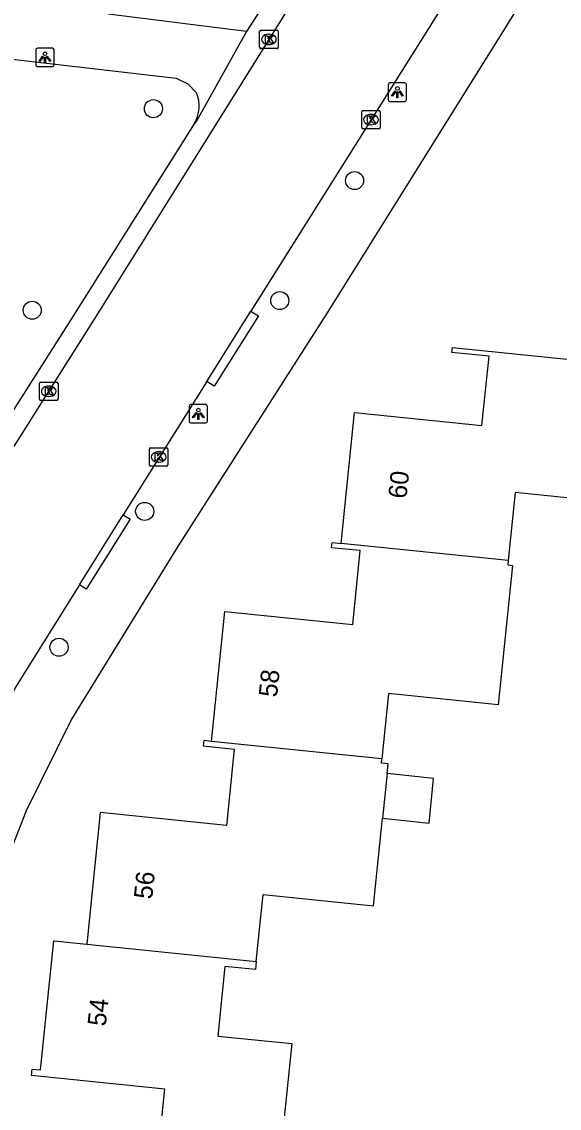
# Model space of a CAD drawing. Extents: x 162398 to 163643, y 386453 to 387397.
# Drawn here: x 162917.5 to 162946.6, y 386956.9 to 387015.8 of the extents above; entities that cross this region are included whole.
import ezdxf

# ---------------------------------------------------------------- set-up
doc = ezdxf.new("R2010")
doc.units = 0
for name, color, linetype in [('IMGEO_Boom', 7, 'Continuous'), ('IMGEO_Kolk', 7, 'Continuous'), ('IMGEO_Lichtpunt', 7, 'Continuous'), ('IMGEO_Pand', 7, 'Continuous'), ('IMGEO_Pand_nummerreeks', 7, 'Continuous'), ('IMGEO_Rijbaan_lokaal_open', 7, 'Continuous'), ('IMGEO_Voetpad_open', 7, 'Continuous')]:
    doc.layers.add(name, color=color, linetype=linetype)

msp = doc.modelspace()

# ---------------------------------------------------------------- linework, layer by layer
at = {"layer": 'IMGEO_Boom'}
for centre in [(162924.653, 387011.052), (162935.55, 387007.16), (162931.497, 387000.658), (162918.093, 387000.138), (162924.183, 386989.242), (162919.544, 386981.885)]:
    msp.add_circle(centre, 0.489, dxfattribs=at)
at = {"layer": 'IMGEO_Kolk'}
for p, q in [((162930.408, 387014.377), (162930.408, 387015.229)), ((162930.483, 387015.303), (162931.335, 387015.303)), ((162931.409, 387015.229), (162931.409, 387014.377)), ((162930.896, 387015.083), (162930.921, 387015.083)), ((162931.335, 387014.303), (162930.483, 387014.303)), ((162930.919, 387014.523), (162930.894, 387014.523)), ((162935.937, 387010.033), (162935.937, 387010.885)), ((162936.012, 387010.959), (162936.864, 387010.959)), ((162936.425, 387010.739), (162936.45, 387010.739)), ((162936.938, 387010.885), (162936.938, 387010.033)), ((162936.864, 387009.959), (162936.012, 387009.959)), ((162936.448, 387010.179), (162936.423, 387010.179)), ((162918.489, 386995.323), (162918.489, 386996.175)), ((162918.564, 386996.249), (162919.416, 386996.249)), ((162918.977, 386996.029), (162919.002, 386996.029)), ((162919.49, 386996.175), (162919.49, 386995.323)), ((162919.416, 386995.249), (162918.564, 386995.249)), ((162919, 386995.469), (162918.975, 386995.469)), ((162924.438, 386991.763), (162924.438, 386992.615)), ((162924.513, 386992.689), (162925.365, 386992.689)), ((162924.926, 386992.469), (162924.951, 386992.469)), ((162925.439, 386992.615), (162925.439, 386991.763)), ((162925.365, 386991.689), (162924.513, 386991.689)), ((162924.949, 386991.909), (162924.924, 386991.909))]:
    msp.add_line(p, q, dxfattribs=at)
for points in [[(162930.408, 387014.377), (162930.408, 387015.229)], [(162930.483, 387015.303), (162931.335, 387015.303)], [(162931.409, 387015.229), (162931.409, 387014.377)], [(162930.729, 387015.003), (162930.852, 387015.003), (162930.852, 387014.852), (162930.982, 387015.003), (162931.146, 387015.003), (162931, 387014.852), (162931.153, 387014.603), (162931.001, 387014.603), (162930.916, 387014.767), (162930.852, 387014.7), (162930.852, 387014.603), (162930.729, 387014.603), (162930.729, 387015.003)], [(162931.335, 387014.303), (162930.483, 387014.303)], [(162935.937, 387010.033), (162935.937, 387010.885)], [(162936.012, 387010.959), (162936.864, 387010.959)], [(162936.258, 387010.659), (162936.381, 387010.659), (162936.381, 387010.508), (162936.511, 387010.659), (162936.675, 387010.659), (162936.529, 387010.508), (162936.682, 387010.259), (162936.53, 387010.259), (162936.445, 387010.423), (162936.381, 387010.356), (162936.381, 387010.259), (162936.258, 387010.259), (162936.258, 387010.659)], [(162936.938, 387010.885), (162936.938, 387010.033)], [(162936.864, 387009.959), (162936.012, 387009.959)], [(162918.489, 386995.323), (162918.489, 386996.175)], [(162918.564, 386996.249), (162919.416, 386996.249)], [(162918.81, 386995.949), (162918.933, 386995.949), (162918.933, 386995.798), (162919.063, 386995.949), (162919.227, 386995.949), (162919.081, 386995.798), (162919.234, 386995.549), (162919.082, 386995.549), (162918.997, 386995.713), (162918.933, 386995.646), (162918.933, 386995.549), (162918.81, 386995.549), (162918.81, 386995.949)], [(162919.49, 386996.175), (162919.49, 386995.323)], [(162919.416, 386995.249), (162918.564, 386995.249)], [(162924.438, 386991.763), (162924.438, 386992.615)], [(162924.513, 386992.689), (162925.365, 386992.689)], [(162924.759, 386992.389), (162924.882, 386992.389), (162924.882, 386992.238), (162925.012, 386992.389), (162925.176, 386992.389), (162925.03, 386992.238), (162925.183, 386991.989), (162925.031, 386991.989), (162924.946, 386992.153), (162924.882, 386992.086), (162924.882, 386991.989), (162924.759, 386991.989), (162924.759, 386992.389)], [(162925.439, 386992.615), (162925.439, 386991.763)], [(162925.365, 386991.689), (162924.513, 386991.689)]]:
    msp.add_lwpolyline(points, dxfattribs=at)
for centre, start, end in [((162930.485, 387015.227), 91.55205, 178.44795), ((162930.485, 387015.227), 91.55205, 178.44795), ((162931.333, 387015.227), 1.55205, 88.44795), ((162931.333, 387015.227), 1.55205, 88.44795), ((162930.485, 387014.379), 181.55205, 268.44795), ((162930.485, 387014.379), 181.55205, 268.44795), ((162931.333, 387014.379), 271.55205, 358.44795), ((162931.333, 387014.379), 271.55205, 358.44795), ((162936.014, 387010.883), 91.55205, 178.44795), ((162936.014, 387010.883), 91.55205, 178.44795), ((162936.862, 387010.883), 1.55205, 88.44795), ((162936.862, 387010.883), 1.55205, 88.44795), ((162936.014, 387010.035), 181.55205, 268.44795), ((162936.014, 387010.035), 181.55205, 268.44795), ((162936.862, 387010.035), 271.55205, 358.44795), ((162936.862, 387010.035), 271.55205, 358.44795), ((162918.566, 386996.173), 91.55205, 178.44795), ((162918.566, 386996.173), 91.55205, 178.44795), ((162919.414, 386996.173), 1.55205, 88.44795), ((162919.414, 386996.173), 1.55205, 88.44795), ((162918.566, 386995.325), 181.55205, 268.44795), ((162918.566, 386995.325), 181.55205, 268.44795), ((162919.414, 386995.325), 271.55205, 358.44795), ((162919.414, 386995.325), 271.55205, 358.44795), ((162924.515, 386992.613), 91.55205, 178.44795), ((162924.515, 386992.613), 91.55205, 178.44795), ((162925.363, 386992.613), 1.55205, 88.44795), ((162925.363, 386992.613), 1.55205, 88.44795), ((162924.515, 386991.765), 181.55205, 268.44795), ((162924.515, 386991.765), 181.55205, 268.44795), ((162925.363, 386991.765), 271.55205, 358.44795), ((162925.363, 386991.765), 271.55205, 358.44795)]:
    msp.add_arc(centre, 0.0765, start, end, dxfattribs=at)
for centre, major_axis, ratio, start_param, end_param in [((162930.895, 387014.803), (-0.387, 0.002), 0.722429, 4.712389, 7.853982), ((162930.92, 387014.803), (-0.39, 0.002), 0.717154, 1.570796, 4.712389), ((162936.424, 387010.459), (-0.387, 0.002), 0.722429, 4.712389, 7.853982), ((162936.449, 387010.459), (-0.39, 0.002), 0.717154, 1.570796, 4.712389), ((162918.976, 386995.749), (-0.387, 0.002), 0.722429, 4.712389, 7.853982), ((162919.001, 386995.749), (-0.39, 0.002), 0.717154, 1.570796, 4.712389), ((162924.925, 386992.189), (-0.387, 0.002), 0.722429, 4.712389, 7.853982), ((162924.95, 386992.189), (-0.39, 0.002), 0.717154, 1.570796, 4.712389)]:
    msp.add_ellipse(centre, major_axis=major_axis, ratio=ratio, start_param=start_param, end_param=end_param, dxfattribs=at)
at = {"layer": 'IMGEO_Lichtpunt'}
for p, q in [((162918.284, 387014.231), (162918.284, 387013.424)), ((162918.284, 387014.231), (162918.284, 387013.424)), ((162919.186, 387014.326), (162918.378, 387014.326)), ((162919.186, 387014.326), (162918.378, 387014.326)), ((162919.28, 387013.424), (162919.28, 387014.231)), ((162919.28, 387013.424), (162919.28, 387014.231)), ((162918.378, 387013.33), (162919.186, 387013.33)), ((162918.378, 387013.33), (162919.186, 387013.33)), ((162937.37, 387012.349), (162937.37, 387011.542)), ((162937.37, 387012.349), (162937.37, 387011.542)), ((162938.272, 387012.444), (162937.464, 387012.444)), ((162938.272, 387012.444), (162937.464, 387012.444)), ((162938.366, 387011.542), (162938.366, 387012.349)), ((162938.366, 387011.542), (162938.366, 387012.349)), ((162937.464, 387011.448), (162938.272, 387011.448)), ((162937.464, 387011.448), (162938.272, 387011.448)), ((162926.588, 386994.931), (162926.588, 386994.124)), ((162926.588, 386994.931), (162926.588, 386994.124)), ((162927.49, 386995.026), (162926.682, 386995.026)), ((162927.49, 386995.026), (162926.682, 386995.026)), ((162927.584, 386994.124), (162927.584, 386994.931)), ((162927.584, 386994.124), (162927.584, 386994.931)), ((162926.682, 386994.03), (162927.49, 386994.03)), ((162926.682, 386994.03), (162927.49, 386994.03))]:
    msp.add_line(p, q, dxfattribs=at)
for points in [[(162918.658, 387013.895), (162918.697, 387013.867), (162918.509, 387013.605), (162918.471, 387013.632), (162918.658, 387013.895)], [(162918.76, 387013.847), (162918.807, 387013.847), (162918.807, 387013.525), (162918.76, 387013.525), (162918.76, 387013.847)], [(162918.87, 387013.867), (162918.908, 387013.894), (162919.095, 387013.632), (162919.056, 387013.604), (162918.87, 387013.867)], [(162937.744, 387012.013), (162937.783, 387011.985), (162937.595, 387011.723), (162937.557, 387011.75), (162937.744, 387012.013)], [(162937.846, 387011.965), (162937.893, 387011.965), (162937.893, 387011.643), (162937.846, 387011.643), (162937.846, 387011.965)], [(162937.956, 387011.985), (162937.994, 387012.012), (162938.181, 387011.75), (162938.142, 387011.722), (162937.956, 387011.985)], [(162926.962, 386994.595), (162927.001, 386994.567), (162926.813, 386994.305), (162926.775, 386994.332), (162926.962, 386994.595)], [(162927.064, 386994.547), (162927.111, 386994.547), (162927.111, 386994.225), (162927.064, 386994.225), (162927.064, 386994.547)], [(162927.174, 386994.567), (162927.212, 386994.594), (162927.399, 386994.332), (162927.36, 386994.304), (162927.174, 386994.567)]]:
    msp.add_lwpolyline(points, dxfattribs=at)
for centre in [(162918.783, 387014.029), (162937.869, 387012.147), (162927.087, 386994.729)]:
    msp.add_circle(centre, 0.0994, dxfattribs=at)
for centre, start, end in [((162918.378, 387014.231), 90, 180), ((162918.378, 387014.231), 90, 180), ((162919.186, 387014.231), 0, 90), ((162919.186, 387014.231), 0, 90), ((162918.378, 387013.424), 180, 270), ((162918.378, 387013.424), 180, 270), ((162919.186, 387013.424), 270, 0), ((162919.186, 387013.424), 270, 360), ((162937.464, 387012.349), 90, 180), ((162937.464, 387012.349), 90, 180), ((162938.272, 387012.349), 0, 90), ((162938.272, 387012.349), 0, 90), ((162937.464, 387011.542), 180, 270), ((162937.464, 387011.542), 180, 270), ((162938.272, 387011.542), 270, 0), ((162938.272, 387011.542), 270, 360), ((162926.682, 386994.931), 90, 180), ((162926.682, 386994.931), 90, 180), ((162927.49, 386994.931), 0, 90), ((162927.49, 386994.931), 0, 90), ((162926.682, 386994.124), 180, 270), ((162926.682, 386994.124), 180, 270), ((162927.49, 386994.124), 270, 0), ((162927.49, 386994.124), 270, 360)]:
    msp.add_arc(centre, 0.0946, start, end, dxfattribs=at)
at = {"layer": 'IMGEO_Pand'}
for points in [[(162934.818, 386987.507), (162935.544, 386994.604), (162942.448, 386993.898), (162942.831, 386997.641), (162940.82, 386997.847), (162940.848, 386998.12), (162945.823, 386997.611), (162950.956, 386997.086), (162950.196, 386989.656), (162944.244, 386990.265), (162943.867, 386986.581)], [(162927.807, 386976.785), (162928.527, 386983.817), (162935.45, 386983.109), (162935.86, 386987.116), (162934.303, 386987.275), (162934.331, 386987.557), (162934.818, 386987.507)], [(162943.867, 386986.581), (162934.818, 386987.507)], [(162943.867, 386986.581), (162943.843, 386986.342), (162944.107, 386986.315), (162943.334, 386978.763), (162937.387, 386979.372), (162937.025, 386975.84)], [(162927.807, 386976.785), (162927.381, 386976.826), (162927.352, 386976.543), (162929.032, 386976.371), (162928.609, 386972.237), (162921.771, 386972.936), (162921.041, 386965.8)], [(162937.025, 386975.84), (162927.807, 386976.785)], [(162937.313, 386975.039), (162937.368, 386975.574), (162937.002, 386975.612), (162937.025, 386975.84)], [(162937.313, 386975.039), (162937.066, 386972.62)], [(162937.066, 386972.62), (162939.583, 386972.362), (162939.83, 386974.781), (162937.313, 386975.039)], [(162930.223, 386964.861), (162930.595, 386968.496), (162936.581, 386967.884), (162937.066, 386972.62)], [(162924.859, 386953.935), (162925.27, 386957.954), (162918.054, 386958.692), (162918.089, 386959.035), (162918.541, 386958.988), (162919.256, 386965.982), (162921.041, 386965.8)], [(162921.041, 386965.8), (162930.223, 386964.861)], [(162930.223, 386964.861), (162930.178, 386964.422), (162928.523, 386964.591), (162928.139, 386960.829), (162932.144, 386960.419), (162931.412, 386953.265)]]:
    msp.add_lwpolyline(points, dxfattribs=at)
at = {"layer": 'IMGEO_Rijbaan_lokaal_open'}
for points in [[(162914.431, 386990.593), (162915.342, 386989.987), (162921.686, 387000.002), (162937.436, 387025.258), (162938.465, 387026.904)], [(162941.722, 387018.853), (162929.936, 387000.092)], [(162927.543, 386996.272), (162929.878, 387000), (162929.936, 387000.092)], [(162927.543, 386996.272), (162923.023, 386989.056)], [(162920.646, 386985.26), (162923.023, 386989.056)], [(162920.646, 386985.26), (162917.178, 386979.724), (162916.277, 386977.92)]]:
    msp.add_lwpolyline(points, dxfattribs=at)
at = {"layer": 'IMGEO_Voetpad_open'}
for points in [[(162942.349, 387034.94), (162940.119, 387031.406), (162929.704, 387015.236)], [(162953.541, 387031.202), (162934.073, 387000), (162925.999, 386987.383), (162920.22, 386977.995), (162917.756, 386973.029), (162916.265, 386969.23), (162904.686, 386937.076)], [(162929.704, 387015.236), (162922.211, 387016.169)], [(162929.704, 387015.236), (162926.997, 387010.375), (162926.857, 387010.23)], [(162914.492, 387014.016), (162925.893, 387012.701), (162926.511, 387012.406), (162926.981, 387011.909)], [(162926.857, 387010.23), (162920.419, 387000), (162914.431, 386990.593)], [(162929.936, 387000.092), (162930.083, 387000), (162930.338, 386999.84), (162927.95, 386996.017), (162927.543, 386996.272)], [(162923.023, 386989.056), (162923.391, 386988.824), (162921.014, 386985.028), (162920.646, 386985.26)]]:
    msp.add_lwpolyline(points, dxfattribs=at)
msp.add_arc((162925.346, 387011.186), 1.788, 327.68772, 23.86463, dxfattribs=at)

# ---------------------------------------------------------------- texts
at = {"layer": 'IMGEO_Pand_nummerreeks'}
for s, rotation, p in [('60', 84.15914, (162938.36, 386989.902)), ('58', 84.15556, (162931.346, 386979.147)), ('56', 84.16177, (162924.586, 386968.212)), ('54', 84.1629, (162922.077, 386961.329))]:
    msp.add_text(s, height=1, rotation=rotation, dxfattribs=at).set_placement(p)

doc.saveas('drawing.dxf')
